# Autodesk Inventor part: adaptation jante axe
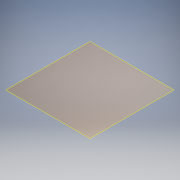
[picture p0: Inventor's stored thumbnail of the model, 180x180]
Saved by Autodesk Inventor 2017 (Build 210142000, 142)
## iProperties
Part Number: adaptation jante axe
Material: Générique
Document SubType Name: Modeling
Designer: ficho
Density: 1 g/cm^3
Appearance: Par défaut
Author: ficho
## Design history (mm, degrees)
node "Plan de construction1"
